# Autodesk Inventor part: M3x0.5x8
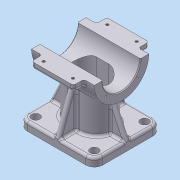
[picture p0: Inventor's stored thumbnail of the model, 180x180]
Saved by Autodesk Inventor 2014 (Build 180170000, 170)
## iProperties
Company: 한국ATC센터
Created: 2009-02
Part Number: M3x0.5x8
Document SubType Name: Modeling
Designer: KYOUNG IL JANG
Density: 2.71 g/cm^3
Material: 알루미늄-6061
Vendor: CBT Solutions
Appearance: 알루미늄 - 평지
Author: KYOUNG IL JANG
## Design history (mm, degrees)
sketch "스케치1"
  geometry: L1 (-45, 40)-(45, 40); L2 (45, 40)-(45, -40); L3 (45, -40)-(-45, -40); L4 (-45, -40)-(-45, 40); 3 further points
  constraints: 8 end point, 2 midpoint, 2 parallel, 1 horizontal, 1 horizontal alignment, 1 perpendicular, 1 vertical alignment
  dimensions: "d0" = 90 distance of L2.end L3.end; "d1" = 80 distance of L1.end L2.end
extrude "돌출1" new body sketch "스케치1" distance "d2" = 10; taper "d3" = 0 deg
sketch "스케치2"
  geometry: L1 (40, 0)-(-40, 0) reference; C1 r 32.5 at (0, 80); 2 further points
  constraints: 1 centre point, 1 midpoint, 1 vertical alignment
  dimensions: "d4" = 65 diameter of C1; "d5" = 80 distance from line of C1.centre L1
extrude "돌출2" join sketch "스케치2" stored distance "d6" = 75; taper "d7" = 0 deg
sketch "스케치3"
  geometry: L1 (-7.5, -20)-(7.5, -20); L2 (7.5, 20)-(-7.5, 20); A1 r 20 centre (7.5, 0) between (7.5, -20) and (7.5, 20); A2 r 20 centre (-7.5, 0) between (-7.5, 20) and (-7.5, -20); 2 further points
  constraints: 4 end point, 4 point on circle, 4 tangent, 2 centre point, 1 horizontal, 1 horizontal alignment, 1 midpoint, 1 parallel, 1 vertical alignment
  dimensions: "d8" = 20 radius of A2; "d9" = 55 dimension on A1 A2
extrude "돌출3" join sketch "스케치3" stored distance "d10" = 75; taper "d11" = 0 deg
fillet "모깎기1" dims "d12" = 10
sketch "스케치4"
  geometry: L1 (-45, 0)-(-45, 10) reference; L2 (37.5, 47.5)-(-37.5, 47.5) reference; L3 (-45, 10)-(-27.513, 47.5); 1 further point
  constraints: 2 end point, 1 point on line
  dimensions: "d13" = 25 deg angle of L3 L1
sketch "스케치5"
  geometry: L1 (-40, 0)-(-40, 10) reference; L2 (-40, 10)-(-22.912, 56.95); 2 further points
  constraints: 2 end point, 2 other
  dimensions: "d14" = 20 deg angle of L2 L1
feature "리브1" dims "d15" = 1, "d16" = 6, "d17" = 0
feature "리브2" dims "d18" = 1, "d19" = 6, "d20" = 0
fillet "모깎기2" dims "d21" = 3
fillet "모깎기3" dims "d22" = 3
fillet "모깎기4" dims "d23" = 3
fillet "모깎기5" dims "d24" = 3
fillet "모깎기6" dims "d25" = 3
fillet "모깎기7" dims "d26" = 3
fillet "모깎기8" dims "d27" = 3
sketch "스케치6"
  geometry: A1 r 10 centre (35, -30) between (35, -40) and (45, -30) reference; 1 further point
hole "구멍1" sketch "스케치6" at (35, -30) diameter "d28" = 10; stored, may be unused: countersink angle "d32" = 90 deg, drill point angle "d34" = 118 deg; dims "d29" = 6, "d30" = 4, "d31" = 2, "d33" = 8
hole "구멍2" diameter "d37" = 45; stored, may be unused: countersink angle "d41" = 90 deg, drill point angle "d43" = 118 deg; dims "d35" = 10, "d36" = 10, "d38" = 6, "d39" = 4, "d40" = 2, "d42" = 8
sketch "스케치7"
  geometry: C1 r 22.5 at (0, 0) reference; 2 further points
  dimensions: "d44" = 135 deg dimension on C1.centre point (-18.738, 18.738) point (80, 0); "d45" = 26.5 distance of point (-18.738, 18.738) C1.centre
hole "구멍3" sketch "스케치7" at (-18.738, 18.738) diameter "d46" = 2.459; stored, may be unused: countersink angle "d50" = 90 deg, drill point angle "d52" = 118 deg; dims "d47" = 8, "d48" = 4, "d49" = 2, "d51" = 10
node "작업 평면1"
sketch "스케치8"
  geometry: C1 r 10 at (0, 0); 1 further point
  constraints: 1 centre point, 1 coincident
  dimensions: "d57" = 20 diameter of C1
extrude "돌출4" join sketch "스케치8" stored distance "d58" = 75; taper "d59" = 0 deg
hole "구멍4" diameter "d62" = 8.376; stored, may be unused: countersink angle "d66" = 90 deg, drill point angle "d68" = 118 deg; dims "d60" = 10, "d61" = 10, "d63" = 7, "d64" = 4, "d65" = 2, "d67" = 10
chamfer "모따기1" distance "d69" = 1; stored, may be unused: second distance "d70" = 2, angle "d71" = 45 deg
fillet "모깎기9" dims "d72" = 3
sketch "스케치9"
  geometry: L1 (-31.623, 87.5)-(-45, 87.5); L2 (-45, 87.5)-(-45, 72.5); L3 (-45, 72.5)-(-31.623, 72.5); A1 r 32.5 centre (0, 80) between (-31.623, 87.5) and (-31.623, 72.5) reference; 1 further point
  constraints: 6 end point, 2 parallel, 2 point on circle, 1 horizontal, 1 perpendicular
  dimensions: "d73" = 15 distance of L1.end L2.end; "d74" = 45 distance from line of A1.centre L2
extrude "돌출5" join sketch "스케치9" stored distance "d75" = 50; taper "d76" = 0 deg
fillet "모깎기10" dims "d77" = 3
fillet "모깎기11" dims "d78" = 3
sketch "스케치10"
  geometry: L1 (-61.625, 62.366)-(0, 62.366); L2 (0, 62.366)-(0, -62.366); L3 (0, -62.366)-(-61.625, -62.366); L4 (-61.625, -62.366)-(-61.625, 62.366); C1 r 32.5 at (0, 0) reference; 2 further points
  constraints: 8 end point, 2 parallel, 1 coincident, 1 horizontal, 1 midpoint, 1 perpendicular
extrude "돌출6" cut sketch "스케치10" stored distance "d79" = 10; taper "d80" = 0 deg
node "작업 평면2"
sketch "스케치11"
  geometry: L1 (-7.5, -15)-(7.5, -15); L2 (7.5, 15)-(-7.5, 15); A1 r 20 centre (-7.5, 0) between (-7.5, 20) and (-26.807, 5.217) reference; A2 r 20 centre (7.5, 0) between (26.807, 5.217) and (7.5, 20) reference; A3 r 15 centre (7.5, 0) between (7.5, -15) and (7.5, 15); A4 r 15 centre (-7.5, 0) between (-7.5, 15) and (-7.5, -15); 1 further point
  constraints: 4 end point, 4 point on circle, 3 tangent, 2 centre point, 2 coincident, 1 horizontal, 1 parallel
  dimensions: "d82" = 15 radius of A4
extrude "돌출7" cut sketch "스케치11" stored distance "d83" = 10; taper "d84" = 0 deg
sketch "스케치12"
  geometry: 1 further point
hole "구멍5" sketch "스케치12" at (0, 0) diameter "d85" = 12; stored, may be unused: countersink angle "d89" = 90 deg, drill point angle "d91" = 118 deg; dims "d86" = 6, "d87" = 38, "d88" = 10, "d90" = 8
sketch "스케치13"
  geometry: L1 (-15.5, -12.5)-(-59.5, -12.5) reference; 3 further points
  constraints: 1 horizontal alignment
  dimensions: "d92" = 35 distance of point (-20, -5.5) point (-55, -5.5); "d93" = 17.5 horizontal distance of point (-37.5, 32.5) point (-55, -5.5) (= 0.5 x d92); "d94" = 7 distance from line of L1 point (-55, -5.5)
hole "구멍6" sketch "스케치13" at (-55, -5.5), (-20, -5.5) diameter "d95" = 3.242; stored, may be unused: countersink angle "d99" = 90 deg, drill point angle "d101" = 118 deg; dims "d96" = 6, "d97" = 38, "d98" = 10, "d100" = 8
sketch "스케치14"
  geometry: C1 r 10 at (0, 0); 1 further point
  constraints: 1 centre point, 1 coincident
  dimensions: "d102" = 20 diameter of C1
extrude "돌출8" cut sketch "스케치14" distance "d103" = 5; taper "d104" = 0 deg
node "솔리드1"
mirror "대칭1"
mirror "대칭2"
mirror "대칭3"
mirror "대칭4"
pattern_circular "원형 패턴1" dims angle "d54" = 360 deg
mirror "대칭5"
mirror "대칭6"
mirror "대칭7"
other parameters: "d56" = -117
